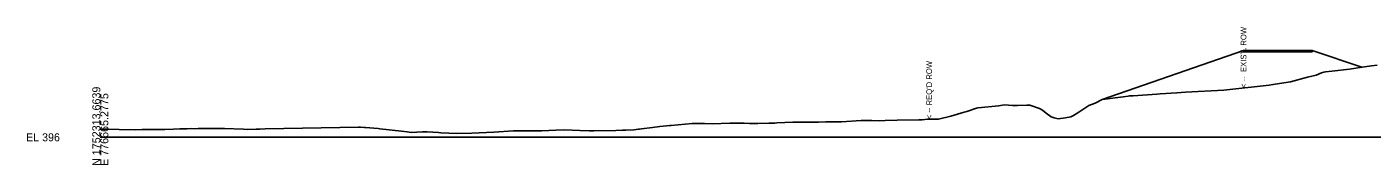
# Model space of a CAD drawing. Extents: x 776426 to 854588, y 1736205 to 1756790.
# Drawn here: x 805845.1 to 806315.8, y 1752205.1 to 1752253.3 of the extents above; entities that cross this region are included whole.
import ezdxf

# ---------------------------------------------------------------- set-up
doc = ezdxf.new("R2010")
doc.units = 0
for name, color, linetype in [('DTM CONTOURS_MAJOR_TX', 7, 'Continuous'), ('DTM_X_FLOW_ARROWS', 7, 'Continuous'), ('XS_P_DR_GRAVEL', 7, 'Continuous'), ('XS_P_GROUND', 7, 'Continuous'), ('XS_P_ROW', 7, 'Continuous'), ('XS_X_ROW', 7, 'Continuous')]:
    doc.layers.add(name, color=color, linetype=linetype)

msp = doc.modelspace()

# ---------------------------------------------------------------- linework, layer by layer
at = {"layer": 'DTM CONTOURS_MAJOR_TX'}
msp.add_line((805870.79, 1752214.76), (806370.79, 1752214.76), dxfattribs=at)
at = {"layer": 'DTM_X_FLOW_ARROWS'}
msp.add_lwpolyline([(805870.79, 1752217.59), (805873.64, 1752217.58), (805877.41, 1752217.46), (805883, 1752217.41), (805885.41, 1752217.53), (805890.97, 1752217.47), (805892.59, 1752217.48), (805893.31, 1752217.51), (805896.43, 1752217.62), (805898.55, 1752217.7), (805899.48, 1752217.7), (805901.2, 1752217.75), (805902.61, 1752217.78), (805903.76, 1752217.77), (805905.03, 1752217.8), (805906.24, 1752217.83), (805907.44, 1752217.8), (805908.65, 1752217.82), (805913.38, 1752217.78), (805914.18, 1752217.79), (805920.87, 1752217.58), (805922.44, 1752217.53), (805925.28, 1752217.59), (805925.93, 1752217.62), (805926.57, 1752217.65), (805928.48, 1752217.7), (805961.16, 1752218.28), (805961.85, 1752218.26), (805963.26, 1752218.21), (805963.62, 1752218.21), (805968.05, 1752217.78), (805968.59, 1752217.7), (805976.18, 1752216.86), (805978.17, 1752216.61), (805979.5, 1752216.42), (805983.5, 1752216.71), (805984, 1752216.71), (805985.18, 1752216.67), (805989.11, 1752216.4), (805989.91, 1752216.37), (805995.55, 1752216.14), (806000.74, 1752216.2), (806008.44, 1752216.57), (806015.38, 1752217), (806018.64, 1752217.02), (806025.24, 1752216.97), (806030.15, 1752217.21), (806033.32, 1752217.31), (806038.6, 1752217.09), (806041.9, 1752217), (806043.5, 1752216.99), (806051.16, 1752217.17), (806053.52, 1752217.21), (806054.66, 1752217.25), (806057.43, 1752217.42), (806059.06, 1752217.62), (806059.44, 1752217.65), (806060.13, 1752217.74), (806064.04, 1752218.23), (806066.53, 1752218.51), (806070.04, 1752218.84), (806070.5, 1752218.87), (806077.87, 1752219.54), (806078.4, 1752219.59), (806082.24, 1752219.55), (806084.82, 1752219.47), (806091.09, 1752219.64), (806092.31, 1752219.68), (806093.18, 1752219.69), (806096.06, 1752219.64), (806097.92, 1752219.63), (806099.83, 1752219.59), (806100.88, 1752219.58), (806104.69, 1752219.68), (806106.82, 1752219.75), (806107.44, 1752219.8), (806113.06, 1752220.03), (806122.02, 1752220.05), (806124.66, 1752220.12), (806130.08, 1752220.13), (806137.04, 1752220.57), (806140.71, 1752220.6), (806143.39, 1752220.5), (806145.37, 1752220.6), (806149.61, 1752220.79), (806157.17, 1752220.86), (806158.29, 1752220.87), (806160.18, 1752221.07), (806164.12, 1752221.1), (806168.36, 1752222.12), (806173.1, 1752223.52), (806173.49, 1752223.61), (806173.96, 1752223.77), (806177.31, 1752224.88), (806177.92, 1752225.08), (806185.03, 1752225.75), (806187.17, 1752226.12), (806190, 1752225.83), (806191.68, 1752225.88), (806195.02, 1752225.95), (806196.01, 1752225.96), (806199.44, 1752224.78), (806200.4, 1752224.26), (806201.76, 1752223.13), (806203.48, 1752221.96), (806204.52, 1752221.51), (806205.98, 1752221.2), (806208.46, 1752221.59), (806210.41, 1752221.86), (806211.35, 1752222.37), (806213.13, 1752223.56), (806216.68, 1752225.86), (806218.83, 1752226.7), (806221.33, 1752227.93), (806228.68, 1752228.94), (806230.44, 1752229.17), (806230.91, 1752229.24), (806232.23, 1752229.28), (806240.5, 1752229.79), (806241.62, 1752229.94), (806247.42, 1752230.24), (806250.45, 1752230.55), (806263.86, 1752231.23), (806279.8, 1752232.95), (806281.07, 1752233.16), (806281.83, 1752233.29), (806287.24, 1752234.14), (806293.15, 1752235.7), (806296.25, 1752236.51), (806298.07, 1752237.31), (806298.92, 1752237.49), (806299.52, 1752237.63), (806301.74, 1752237.9), (806307.89, 1752238.55), (806312.26, 1752239.27), (806315.57, 1752239.69), (806317.53, 1752239.97)], dxfattribs=at)
at = {"layer": 'XS_P_DR_GRAVEL'}
for points in [[(806282.79, 1752245.08), (806282.79, 1752244.58), (806270.79, 1752244.58), (806270.79, 1752245.08), (806282.79, 1752245.08)], [(806282.79, 1752245.08), (806282.79, 1752244.58), (806294.79, 1752244.58), (806294.79, 1752245.08), (806282.79, 1752245.08)]]:
    msp.add_lwpolyline(points, dxfattribs=at)
at = {"layer": 'XS_P_GROUND'}
for points in [[(806270.79, 1752245.08), (806221.33, 1752227.93)], [(806294.79, 1752245.08), (806312.24, 1752239.27)]]:
    msp.add_lwpolyline(points, dxfattribs=at)

# ---------------------------------------------------------------- texts
at = {"layer": 'DTM CONTOURS_MAJOR_TX'}
for s, p in [('N 1752313.6639', (805870.79, 1752204.76)), ('E 776665.2775', (805873.59, 1752204.76))]:
    msp.add_text(s, height=2.8, rotation=90, dxfattribs=at).set_placement(p)
msp.add_text('EL 396', height=2.8, dxfattribs=at).set_placement((805844.79, 1752213.36))
at = {"layer": 'XS_P_ROW'}
msp.add_text("< -- REQ'D ROW", height=2, rotation=90, dxfattribs=at).set_placement((806161.79, 1752221.07))
at = {"layer": 'XS_X_ROW'}
msp.add_text('< --  EXIST. ROW', height=2, rotation=90, dxfattribs=at).set_placement((806271.79, 1752231.98))

doc.saveas('drawing.dxf')
